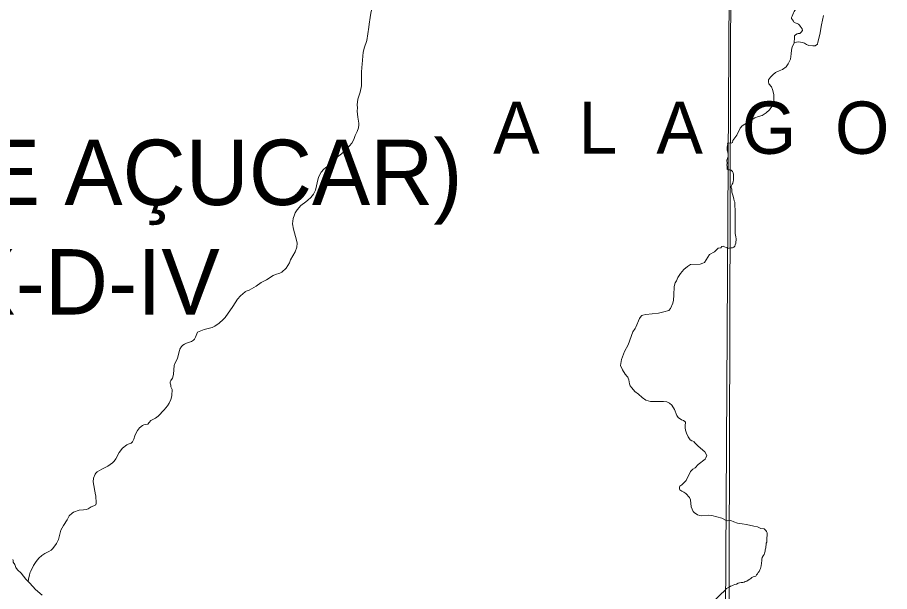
# Model space of a CAD drawing. Extents: x 553962 to 842807, y 8883888 to 9032388.
# Drawn here: x 602106 to 608778, y 8901395 to 8905786 of the extents above; entities that cross this region are included whole.
import ezdxf

# ---------------------------------------------------------------- set-up
doc = ezdxf.new("R2010")
doc.units = 0
doc.header["$LTSCALE"] = 200
doc.layers.add('6', color=7, linetype='Continuous', lineweight=13)

msp = doc.modelspace()

# ---------------------------------------------------------------- linework, layer by layer
at = {"layer": '6'}
for points in [[(607657.7, 8924743.3), (607574.2, 8909874.9), (607492.3, 8896026.7)], [(604804.8, 8905785.5), (604809.3, 8905818.8), (604816.7, 8905853), (604826.7, 8905886.2), (604829.3, 8905902), (604842.4, 8905936.1), (604843.2, 8905939.8)], [(608074.9, 8905864.8), (608071.3, 8905854.9), (608059.1, 8905846.8), (608048.8, 8905832.6), (608043.6, 8905820.4), (608038.4, 8905808.2), (608034.3, 8905796), (608029.1, 8905786.9), (608027.2, 8905782.8)], [(608273, 8905800.4), (608256.6, 8905729.8), (608243.7, 8905656.1), (608230.5, 8905597.6), (608226.1, 8905583), (608210.1, 8905568.4), (608191.1, 8905568.4), (608160.5, 8905571.3), (608142.9, 8905580.1), (608126.9, 8905590.3), (608112.3, 8905594.7), (608081.6, 8905599.1), (608067, 8905597.6), (608049.5, 8905591.8), (608043.7, 8905578.7), (608032, 8905562.6), (608027.6, 8905536.3), (608026.2, 8905507), (608020.3, 8905467.6), (608002.8, 8905431.1), (607986.8, 8905409.1), (607960.5, 8905387.2), (607932.7, 8905378.4), (607905.4, 8905365.4), (607886, 8905347.8), (607868.5, 8905328.8), (607851, 8905309.8), (607851, 8905293.7), (607855.4, 8905279.1), (607874.3, 8905255.7), (607883.1, 8905233.8), (607891.9, 8905197.2), (607891.9, 8905149), (607883.1, 8905112.5), (607859.8, 8905078.9), (607834.9, 8905055.5), (607802.8, 8905035.1), (607776.5, 8905027.7), (607748.8, 8905019), (607649.6, 8904956.1), (607636.4, 8904938.6), (607608.8, 8904885.8), (607578.6, 8904845.8), (607576.8, 8904829.7), (607565.2, 8904825.7), (607544.2, 8904827.2)], [(604778.2, 8905608.6), (604794.2, 8905712.3), (604795.5, 8905733.7), (604804.8, 8905785.5)], [(604778.2, 8905608.6), (604794.2, 8905712.3), (604795.5, 8905733.7), (604804.8, 8905785.5)], [(608027.2, 8905782.8), (608027.3, 8905777.6), (608035.4, 8905768.4), (608042.5, 8905758.1), (608047.5, 8905747.9), (608056.6, 8905743.8), (608070.8, 8905740.7), (608081, 8905734.5), (608089, 8905727.3), (608095.1, 8905719.1), (608103.2, 8905709.9), (608110.2, 8905698.7), (608111.1, 8905685.4), (608102.9, 8905673.2), (608090.6, 8905664.1), (608079.5, 8905664.2), (608070.3, 8905660.2), (608059, 8905653.1), (608051.8, 8905645), (608051.8, 8905632.8), (608049.5, 8905591.8)], [(604747.8, 8905493.6), (604750.5, 8905517), (604757.5, 8905551.2), (604778.2, 8905608.6)], [(604747.8, 8905493.6), (604750.5, 8905517), (604757.5, 8905551.2), (604778.2, 8905608.6)], [(604327.6, 8904389.5), (604350.5, 8904410.1), (604371.6, 8904435.8), (604385.3, 8904465.2), (604405.7, 8904555.3), (604411.1, 8904568.9), (604429.1, 8904602.9), (604450.2, 8904627), (604475.1, 8904645.9), (604525.5, 8904700.2), (604584.4, 8904742.2), (604605.7, 8904760.1), (604646.5, 8904803), (604663.6, 8904825), (604679, 8904851.8), (604690.7, 8904882.5), (604705.3, 8904913.2), (604714.1, 8904941), (604718.5, 8904964.3), (604718.5, 8904977.4), (604709.8, 8905023.9), (604706.1, 8905068.4), (604707.9, 8905095.1), (604704.2, 8905117.3), (604710.1, 8905160.8), (604728.9, 8905215.6), (604737.1, 8905262.8), (604738.6, 8905285.2), (604737.8, 8905368.5), (604740.1, 8905402.7), (604744.1, 8905428.6), (604747.3, 8905489.6), (604747.8, 8905493.6)], [(604327.6, 8904389.5), (604350.5, 8904410.1), (604371.6, 8904435.8), (604385.3, 8904465.2), (604405.7, 8904555.3), (604411.1, 8904568.9), (604429.1, 8904602.9), (604450.2, 8904627), (604475.1, 8904645.9), (604525.5, 8904700.2), (604584.4, 8904742.2), (604605.7, 8904760.1), (604646.5, 8904803), (604663.6, 8904825), (604679, 8904851.8), (604690.7, 8904882.5), (604705.3, 8904913.2), (604714.1, 8904941), (604718.5, 8904964.3), (604718.5, 8904977.4), (604709.8, 8905023.9), (604706.1, 8905068.4), (604707.9, 8905095.1), (604704.2, 8905117.3), (604710.1, 8905160.8), (604728.9, 8905215.6), (604737.1, 8905262.8), (604738.6, 8905285.2), (604737.8, 8905368.5), (604740.1, 8905402.7), (604744.1, 8905428.6), (604747.3, 8905489.6), (604747.8, 8905493.6)], [(607533.6, 8904693.8), (607536.3, 8904667.9), (607534.5, 8904658.1), (607535.4, 8904643.6), (607536.9, 8904625.2), (607543, 8904621.2)], [(607543, 8904621.2), (607555.3, 8904621.2), (607567.5, 8904618), (607576.6, 8904606.8), (607580.6, 8904597.6), (607583.5, 8904584.3), (607583.5, 8904574.1), (607584.4, 8904563.9), (607585.3, 8904552.7), (607585.3, 8904541.5), (607581.1, 8904530.3), (607580, 8904518.1), (607573, 8904511.2), (607565.9, 8904494.7), (607566.7, 8904484.5), (607572.6, 8904473.3), (607572.5, 8904463.1), (607572.4, 8904449.9), (607579.4, 8904426.4), (607587.3, 8904397.8), (607590.3, 8904384.6), (607593.3, 8904373.3), (607594.2, 8904361.1), (607594.1, 8904345.8), (607595, 8904335.6), (607596, 8904324.4), (607596.9, 8904313.2), (607596.8, 8904300), (607596.8, 8904288.8), (607596.7, 8904276.5), (607596.6, 8904265.3), (607596.5, 8904253.1), (607596.4, 8904239.9), (607596.3, 8904225.6), (607596.2, 8904214.4), (607596.1, 8904201.2), (607596, 8904184.9), (607596.9, 8904169.6), (607596.9, 8904157.3), (607596.8, 8904144.1), (607597.7, 8904133.9), (607600.7, 8904120.7), (607602.6, 8904108.4), (607603.5, 8904094.1), (607603.5, 8904082.9), (607603.4, 8904070.7), (607603.3, 8904059.5), (607598.1, 8904048.3), (607594, 8904037.2), (607587.8, 8904029), (607576.6, 8904025), (607565.4, 8904023.1), (607551.2, 8904022.1), (607539.5, 8904022.2)], [(603848.5, 8903689.3), (603879.4, 8903699.9), (603932.5, 8903731.3), (603970.9, 8903758.4), (604011.4, 8903779.7), (604062.1, 8903811.7), (604081.3, 8903819.7), (604112.1, 8903829.5), (604128.1, 8903837.8), (604160.6, 8903868.1), (604188, 8903908.3), (604193.8, 8903933.4), (604229.6, 8903993.3), (604243.1, 8904028.2), (604244.7, 8904060.5), (604241.9, 8904082.8), (604217.8, 8904165.8), (604209.6, 8904208.1), (604216.3, 8904247.2), (604224.6, 8904276.3), (604230.8, 8904292.3), (604245.3, 8904315.6), (604274.7, 8904347.3), (604311.8, 8904375.3), (604327.6, 8904389.5)], [(603848.5, 8903689.3), (603879.4, 8903699.9), (603932.5, 8903731.3), (603970.9, 8903758.4), (604011.4, 8903779.7), (604062.1, 8903811.7), (604081.3, 8903819.7), (604112.1, 8903829.5), (604128.1, 8903837.8), (604160.6, 8903868.1), (604188, 8903908.3), (604193.8, 8903933.4), (604229.6, 8903993.3), (604243.1, 8904028.2), (604244.7, 8904060.5), (604241.9, 8904082.8), (604217.8, 8904165.8), (604209.6, 8904208.1), (604216.3, 8904247.2), (604224.6, 8904276.3), (604230.8, 8904292.3), (604245.3, 8904315.6), (604274.7, 8904347.3), (604311.8, 8904375.3), (604327.6, 8904389.5)], [(607439.6, 8903994.4), (607401.7, 8903974.1), (607363.5, 8903911.4), (607350.2, 8903907.7), (607330.3, 8903899), (607254.4, 8903896.8), (607231.9, 8903881.8), (607205, 8903859.6), (607178.8, 8903827.1), (607158.9, 8903797.1), (607148.6, 8903771.3), (607139.2, 8903755.2), (607130.6, 8903728.9), (607128.7, 8903662.2), (607125.2, 8903625.1), (607119.4, 8903601.2), (607102.3, 8903559), (607089.9, 8903545.3), (607051.9, 8903533.7), (607010.8, 8903525), (606914.4, 8903515.1), (606889.7, 8903509.6), (606883, 8903506.6), (606877.2, 8903501.5), (606866.2, 8903484.8), (606836, 8903417.6), (606832.9, 8903406.8), (606815, 8903380.7), (606778.9, 8903283.1), (606749.9, 8903231.4), (606728.4, 8903170.9), (606719, 8903125.1), (606734, 8903090.3), (606755.2, 8903058.8), (606770.8, 8903040), (606775.7, 8903035.2), (606778.4, 8903028.4)], [(607539.5, 8904022.2), (607505.3, 8904036.4), (607495.6, 8904034.6), (607487.2, 8904025.2), (607466.3, 8904021.2), (607439.6, 8903994.4), (607439.6, 8903994.4)], [(603483.1, 8903378.3), (603483.5, 8903378.8), (603534.8, 8903400.2), (603594.5, 8903414.3), (603616.7, 8903425.6), (603647.8, 8903448.6), (603679.1, 8903476.5), (603694.2, 8903492.2), (603694.2, 8903492.2), (603754.4, 8903576.4), (603788.6, 8903630.3), (603811.4, 8903656.2), (603846.9, 8903688.8), (603848.5, 8903689.3)], [(603483.1, 8903378.3), (603483.5, 8903378.8), (603534.8, 8903400.2), (603594.5, 8903414.3), (603616.7, 8903425.6), (603647.8, 8903448.6), (603679.1, 8903476.5), (603694.2, 8903492.2), (603694.2, 8903492.2), (603754.4, 8903576.4), (603788.6, 8903630.3), (603811.4, 8903656.2), (603846.9, 8903688.8), (603848.5, 8903689.3)], [(603324, 8903166.9), (603330.9, 8903180.3), (603344.7, 8903238.3), (603348.7, 8903249.1), (603360.5, 8903269.5), (603370.1, 8903279.6), (603382.8, 8903288.5), (603399.7, 8903296.2), (603436.4, 8903306.9), (603453.6, 8903318), (603459.7, 8903325.4), (603468.1, 8903340.2), (603483.1, 8903378.3)], [(603324, 8903166.9), (603330.9, 8903180.3), (603344.7, 8903238.3), (603348.7, 8903249.1), (603360.5, 8903269.5), (603370.1, 8903279.6), (603382.8, 8903288.5), (603399.7, 8903296.2), (603436.4, 8903306.9), (603453.6, 8903318), (603459.7, 8903325.4), (603468.1, 8903340.2), (603483.1, 8903378.3)], [(603279.8, 8902962.1), (603280.5, 8902974.6), (603273.5, 8902989.6), (603273.4, 8903000.5), (603278, 8903010.1), (603291.1, 8903028.1), (603297.7, 8903044.9), (603300.5, 8903057.1), (603304.6, 8903125.2), (603311.8, 8903143.4), (603311.8, 8903143.4), (603324, 8903166.9)], [(603279.8, 8902962.1), (603280.5, 8902974.6), (603273.5, 8902989.6), (603273.4, 8903000.5), (603278, 8903010.1), (603291.1, 8903028.1), (603297.7, 8903044.9), (603300.5, 8903057.1), (603304.6, 8903125.2), (603311.8, 8903143.4), (603311.8, 8903143.4), (603324, 8903166.9)], [(606778.4, 8903028.4), (606783.4, 8903013.8), (606788, 8902984.9), (606794.7, 8902968.1), (606806, 8902952.7), (606830.2, 8902925.4), (606857.1, 8902905.1), (606886.3, 8902878.8), (606914.4, 8902860.1), (606948, 8902848.9), (607006.6, 8902848.1), (607048.1, 8902849.7), (607075.3, 8902846.4), (607093.9, 8902836.4), (607113.6, 8902820.6), (607131.9, 8902788.2), (607150.9, 8902742.4), (607162, 8902727.5), (607186, 8902709.2), (607201.3, 8902703.4), (607212.6, 8902696.1), (607216.2, 8902691.5), (607217.8, 8902685.4), (607215.4, 8902668.2), (607214.9, 8902646.2), (607217.1, 8902629.1), (607225.2, 8902606.8), (607238.2, 8902578.9), (607253.8, 8902555.2), (607264.3, 8902547.5), (607282.7, 8902541.7), (607283.6, 8902539), (607302, 8902521), (607314.7, 8902506.1), (607364.1, 8902464.6), (607381.1, 8902437), (607373.8, 8902416.9), (607366.9, 8902407.5), (607313.2, 8902367.6), (607289.9, 8902342.3), (607273.6, 8902332.1), (607256.1, 8902313.6), (607221.8, 8902244.4), (607189.3, 8902212.4), (607173.9, 8902201.2), (607171.6, 8902197.4), (607171.2, 8902181.6), (607174.7, 8902173.2), (607187.8, 8902163.1), (607205.5, 8902155), (607219.1, 8902145.2), (607248.4, 8902113.7), (607254.3, 8902096.2), (607259.3, 8902043.8), (607274.6, 8902007), (607283.9, 8901998.8), (607310.1, 8901983.3), (607326.6, 8901977.4), (607338.1, 8901975.5), (607395.1, 8901979.1), (607418.6, 8901977.9), (607495.8, 8901956.3), (607527.2, 8901939.7)], [(603125.3, 8902703.2), (603125.5, 8902703.4), (603161.9, 8902721.7), (603183.4, 8902737.9), (603227.5, 8902784.5), (603253, 8902814.8), (603266.1, 8902837.2), (603279.3, 8902865.2), (603284.7, 8902880.8), (603287.6, 8902895.8), (603289.1, 8902941.6), (603279.8, 8902961.4), (603279.8, 8902962.1)], [(603125.3, 8902703.2), (603125.5, 8902703.4), (603161.9, 8902721.7), (603183.4, 8902737.9), (603227.5, 8902784.5), (603253, 8902814.8), (603266.1, 8902837.2), (603279.3, 8902865.2), (603284.7, 8902880.8), (603287.6, 8902895.8), (603289.1, 8902941.6), (603279.8, 8902961.4), (603279.8, 8902962.1)], [(602703.6, 8902135.4), (602685.7, 8902235), (602687.1, 8902263.6), (602699.1, 8902292.9), (602704.9, 8902301.3), (602715, 8902311.4), (602750.2, 8902332.5), (602796.9, 8902353.2), (602833.1, 8902379.3), (602845.3, 8902393.6), (602857.7, 8902411.3), (602883.4, 8902457.7), (602910.2, 8902491.3), (602943.5, 8902518.1), (602953.5, 8902523.6), (602974.9, 8902531.3), (602985.9, 8902541), (602995.8, 8902560.9), (603003.1, 8902586.9), (603013.4, 8902609.7), (603023.1, 8902626.2), (603040.1, 8902647.5), (603062.7, 8902666.2), (603071.5, 8902669.3), (603104.3, 8902675.8), (603114.6, 8902687.5), (603125.3, 8902703.2)], [(602703.6, 8902135.4), (602685.7, 8902235), (602687.1, 8902263.6), (602699.1, 8902292.9), (602704.9, 8902301.3), (602715, 8902311.4), (602750.2, 8902332.5), (602796.9, 8902353.2), (602833.1, 8902379.3), (602845.3, 8902393.6), (602857.7, 8902411.3), (602883.4, 8902457.7), (602910.2, 8902491.3), (602943.5, 8902518.1), (602953.5, 8902523.6), (602974.9, 8902531.3), (602985.9, 8902541), (602995.8, 8902560.9), (603003.1, 8902586.9), (603013.4, 8902609.7), (603023.1, 8902626.2), (603040.1, 8902647.5), (603062.7, 8902666.2), (603071.5, 8902669.3), (603104.3, 8902675.8), (603114.6, 8902687.5), (603125.3, 8902703.2)], [(602187.4, 8901471.7), (602189.9, 8901490.4), (602196.8, 8901523.9), (602203.3, 8901543.2), (602229.3, 8901595.1), (602248.3, 8901625.4), (602269.3, 8901650), (602292.3, 8901670.8), (602316.4, 8901686.5), (602346.7, 8901702), (602364, 8901712.7), (602375.5, 8901724.7), (602403.4, 8901763.5), (602419.7, 8901793.9), (602438, 8901864), (602458.8, 8901901.1), (602485.7, 8901943), (602501.1, 8901973.6), (602524, 8901995.8), (602535.5, 8902003.7), (602576.8, 8902019), (602610.6, 8902019.3), (602633.5, 8902022.2), (602647.1, 8902028.6), (602670.3, 8902043.6), (602690.3, 8902050.4), (602701.4, 8902056.2), (602704.6, 8902059.5), (602709, 8902072.5), (602705.2, 8902126.5), (602703.6, 8902135.4)], [(602207.7, 8901552), (602229.3, 8901595.1), (602248.3, 8901625.4), (602269.3, 8901650), (602292.3, 8901670.8), (602316.4, 8901686.5), (602346.7, 8901702), (602364, 8901712.7), (602375.5, 8901724.7), (602403.4, 8901763.5), (602419.7, 8901793.9), (602438, 8901864), (602458.8, 8901901.1), (602485.7, 8901943), (602501.1, 8901973.6), (602524, 8901995.8), (602535.5, 8902003.7), (602576.8, 8902019), (602610.6, 8902019.3), (602633.5, 8902022.2), (602647.1, 8902028.6), (602670.3, 8902043.6), (602690.3, 8902050.4), (602701.4, 8902056.2), (602704.6, 8902059.5), (602709, 8902072.5), (602705.2, 8902126.5), (602703.6, 8902135.4)], [(607527.2, 8901939.7), (607536.2, 8901937), (607536.2, 8901937), (607562.8, 8901938.1), (607562.8, 8901938.1), (607562.8, 8901938.1), (607587.2, 8901928.1)], [(607587.2, 8901928.1), (607614.9, 8901919.2), (607614.9, 8901919.2), (607614.9, 8901919.2), (607614.9, 8901919.2), (607651.6, 8901913.7), (607651.6, 8901913.7), (607651.6, 8901913.7), (607684.9, 8901908.1), (607684.9, 8901908.1), (607684.9, 8901908.1), (607740.3, 8901895.9), (607740.3, 8901895.9), (607740.3, 8901895.9), (607740.3, 8901895.9), (607768.1, 8901890.4), (607768.1, 8901890.4), (607768.1, 8901890.4), (607794.7, 8901878.2), (607818, 8901873.8), (607831.7, 8901862), (607837.7, 8901853.8), (607841.7, 8901843.6), (607841.6, 8901833.4), (607841.6, 8901821.2), (607840.5, 8901808), (607840.4, 8901794.7), (607839.3, 8901784.6), (607839.2, 8901773.3), (607835.1, 8901764.2), (607834, 8901753), (607832.9, 8901740.8), (607830.8, 8901728.6), (607827.6, 8901715.3), (607825.5, 8901705.2), (607821.3, 8901689.9), (607818.2, 8901679.8), (607812, 8901668.6), (607804.8, 8901656.4), (607801.7, 8901644.2), (607800.6, 8901634), (607797.9, 8901612)], [(602070.8, 8901639.8), (602072.5, 8901633.8), (602072, 8901620.7), (602085.6, 8901602.1), (602093.9, 8901578.1), (602106, 8901562.3), (602134.9, 8901535.6), (602168.7, 8901491), (602172.2, 8901488.4), (602197.2, 8901460.9)], [(607797.9, 8901612), (607796.2, 8901592.3), (607794.1, 8901582.1), (607790, 8901570.9), (607786.9, 8901560.8), (607780.7, 8901549.6), (607773.5, 8901540.5), (607768.3, 8901530.3), (607761.2, 8901522.2), (607754, 8901514.1), (607743.8, 8901511.1), (607734.6, 8901507.1), (607724.4, 8901503.1), (607717.2, 8901496), (607710.1, 8901488.9), (607697.8, 8901481.9), (607685.6, 8901474.8), (607674.4, 8901471.8), (607665.2, 8901467.8), (607655, 8901464.8), (607643.8, 8901463.9), (607630.5, 8901460.9), (607620.4, 8901458.9), (607606.1, 8901452.9), (607594.9, 8901449.9), (607582.6, 8901443.9), (607572.4, 8901439.9), (607561.2, 8901436.9), (607551, 8901428.8), (607530.6, 8901418.8), (607518.6, 8901403.9)], [(602197.2, 8901460.9), (602223.4, 8901432.9), (602245, 8901410.9), (602295.9, 8901367.1)], [(607518.6, 8901403.9), (607482.1, 8901370.7), (607412.3, 8901297.6), (607362.4, 8901224.5), (607352.5, 8901188), (607342.5, 8901164.7), (607332.5, 8901088.4), (607319.2, 8901041.9), (607299.3, 8901002), (607289.3, 8900968.8), (607272.7, 8900938.9), (607233.9, 8900903.3)]]:
    msp.add_lwpolyline(points, dxfattribs=at)
msp.add_lwpolyline([(618535.2, 8909853.3), (607574.3, 8909890.7), (607543.3, 8898835.3), (618504.2, 8898795.8)], close=True, dxfattribs=at)
msp.add_spline([(607544.2, 8904827.2), (607540.5, 8904825.6), (607539.7, 8904818), (607536, 8904789.9), (607538.2, 8904764.1), (607543.5, 8904735.3), (607542.8, 8904723.1), (607533.6, 8904694.1)], degree=3, dxfattribs=at)

# ---------------------------------------------------------------- texts
for s, height, p in [('A  L  A  G  O  A  S', 400, (605744.9, 8904743.1)), ('(PÃO DE AÇUCAR)', 500, (599529.4, 8904351.2)), ('SC-24-X-D-IV', 500, (599529.4, 8903514.1))]:
    msp.add_text(s, height=height, dxfattribs=at).set_placement(p)

doc.saveas('drawing.dxf')
